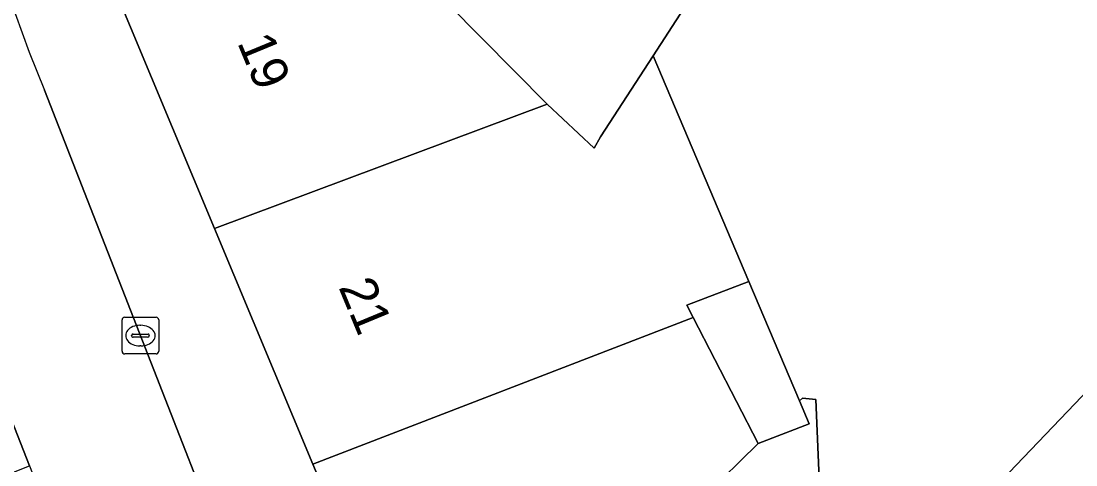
# Model space of a CAD drawing. Extents: x 160663 to 161506, y 382245 to 383291.
# Drawn here: x 161129.57 to 161158.3, y 383146.96 to 383159.05 of the extents above; entities that cross this region are included whole.
import ezdxf

# ---------------------------------------------------------------- set-up
doc = ezdxf.new("R2010")
doc.units = 0
for name, color, linetype in [('IMGEO_Groenvoorziening', 7, 'Continuous'), ('IMGEO_Kolk', 7, 'Continuous'), ('IMGEO_Pand', 7, 'Continuous'), ('IMGEO_Pand_nummerreeks', 7, 'Continuous'), ('IMGEO_Parkeervlak_open', 7, 'Continuous'), ('IMGEO_Voetpad_open', 7, 'Continuous'), ('IMGEO_Woonerf_open', 7, 'Continuous')]:
    doc.layers.add(name, color=color, linetype=linetype)

msp = doc.modelspace()

# ---------------------------------------------------------------- linework, layer by layer
at = {"layer": 'IMGEO_Groenvoorziening'}
for points in [[(161159.601, 383161.046), (161156.987, 383162.473), (161154.786, 383163.643), (161151.498, 383165.39), (161151.378, 383165.212), (161146.783, 383158.104), (161149.389, 383151.959), (161150.771, 383148.7), (161150.848, 383148.779), (161151.214, 383148.74), (161151.442, 383143.355), (161142.883, 383135.27), (161146.227, 383132.301), (161147.528, 383133.493), (161149.889, 383137.24), (161153.216, 383142.573), (161155.564, 383146.324), (161155.876, 383146.12), (161165.215, 383155.885)], [(161166.528, 383154.573), (161166.335, 383154.758), (161165.215, 383155.885), (161155.876, 383146.12), (161157.319, 383145.175), (161162.383, 383149.949), (161166.424, 383153.804)]]:
    msp.add_lwpolyline(points, dxfattribs=at)
at = {"layer": 'IMGEO_Kolk'}
for p, q in [((161132.323, 383150.055), (161132.323, 383150.907)), ((161132.398, 383150.981), (161133.25, 383150.981)), ((161132.811, 383150.761), (161132.836, 383150.761)), ((161133.324, 383150.907), (161133.324, 383150.055)), ((161132.582, 383150.475), (161132.582, 383150.487)), ((161132.625, 383150.524), (161133.023, 383150.524)), ((161133.066, 383150.487), (161133.066, 383150.475)), ((161133.02, 383150.438), (161132.622, 383150.438)), ((161132.834, 383150.201), (161132.809, 383150.201)), ((161133.25, 383149.981), (161132.398, 383149.981))]:
    msp.add_line(p, q, dxfattribs=at)
for points in [[(161132.323, 383150.055), (161132.323, 383150.907)], [(161132.398, 383150.981), (161133.25, 383150.981)], [(161133.324, 383150.907), (161133.324, 383150.055)], [(161133.25, 383149.981), (161132.398, 383149.981)]]:
    msp.add_lwpolyline(points, dxfattribs=at)
for centre, radius, start, end in [((161132.4, 383150.905), 0.0765, 91.552, 178.448), ((161132.4, 383150.905), 0.0765, 91.552, 178.448), ((161133.248, 383150.905), 0.0765, 1.552, 88.448), ((161133.248, 383150.905), 0.0765, 1.552, 88.448), ((161132.622, 383150.484), 0.0403, 85.8775, 175.7526), ((161132.619, 383150.474), 0.0366, 178.938, 274.7102), ((161133.023, 383150.481), 0.043, 264.8664, 352.4533), ((161133.027, 383150.486), 0.0386, 1.7309, 96.639), ((161132.4, 383150.057), 0.0765, 181.552, 268.448), ((161132.4, 383150.057), 0.0765, 181.552, 268.448), ((161133.248, 383150.057), 0.0765, 271.552, 358.448), ((161133.248, 383150.057), 0.0765, 271.552, 358.448)]:
    msp.add_arc(centre, radius, start, end, dxfattribs=at)
for centre, major_axis, ratio, start_param, end_param in [((161132.81, 383150.481), (-0.387, 0.002), 0.722429, 4.712389, 7.853982), ((161132.835, 383150.481), (-0.39, 0.002), 0.717154, 1.570796, 4.712389)]:
    msp.add_ellipse(centre, major_axis=major_axis, ratio=ratio, start_param=start_param, end_param=end_param, dxfattribs=at)
at = {"layer": 'IMGEO_Pand'}
for points in [[(161141.423, 383171.856), (161129.809, 383177.129), (161129.783, 383176.901), (161131.927, 383160.664), (161137.626, 383163.141), (161143.896, 383156.786), (161145.179, 383155.593), (161145.348, 383155.898), (161146.783, 383158.104), (161151.378, 383165.212), (161144.065, 383169.294), (161142.775, 383166.983), (161142.026, 383167.449)], [(161131.927, 383160.664), (161131.982, 383160.267), (161134.843, 383153.401), (161143.896, 383156.786), (161137.626, 383163.141)], [(161146.783, 383158.104), (161145.348, 383155.898), (161145.179, 383155.593), (161143.896, 383156.786), (161134.843, 383153.401), (161137.518, 383146.979), (161147.876, 383150.976), (161147.705, 383151.309), (161149.389, 383151.959)], [(161149.389, 383151.959), (161147.705, 383151.309), (161147.876, 383150.976), (161149.641, 383147.54), (161151.034, 383148.078), (161150.771, 383148.7)], [(161147.876, 383150.976), (161137.518, 383146.979), (161140.874, 383138.924), (161149.641, 383147.54)]]:
    msp.add_lwpolyline(points, close=True, dxfattribs=at)
at = {"layer": 'IMGEO_Parkeervlak_open'}
msp.add_lwpolyline([(161151.442, 383143.355), (161151.214, 383148.74), (161150.848, 383148.779), (161150.771, 383148.7), (161151.034, 383148.078), (161149.641, 383147.54), (161140.874, 383138.924), (161141.404, 383136.895), (161142.883, 383135.27)], close=True, dxfattribs=at)
at = {"layer": 'IMGEO_Voetpad_open'}
msp.add_lwpolyline([(161096.232, 383065.041), (161097.948, 383067.723), (161100.236, 383068.269), (161101.27, 383070.058), (161102.587, 383072.301), (161107.023, 383080.092), (161110.056, 383085.418), (161110.781, 383085.656), (161120.09, 383100.134), (161120.161, 383100.245), (161118.207, 383101.501), (161124.761, 383111.696), (161126.716, 383110.439), (161127.839, 383112.186), (161127.679, 383113.208), (161135.448, 383125.333), (161133.773, 383126.361), (161133.469, 383127.948), (161135.792, 383131.655), (161135.611, 383132.118), (161133.742, 383131.385), (161127.933, 383146.199), (161129.801, 383146.932), (161126.39, 383155.632)], dxfattribs=at)
at = {"layer": 'IMGEO_Woonerf_open'}
for points in [[(161137.518, 383146.979), (161134.843, 383153.401), (161131.982, 383160.267), (161131.927, 383160.664), (161129.783, 383176.901), (161129.809, 383177.129), (161130.489, 383183.198), (161130.789, 383183.88), (161131.314, 383185.435), (161134.132, 383192.246), (161135.412, 383195.339), (161136.378, 383197.673), (161136.869, 383198.648), (161139.406, 383203.684), (161139.801, 383204.468), (161139.653, 383204.63), (161138.74, 383205.154), (161143.158, 383214.429), (161142.031, 383214.987), (161141.728, 383215.125), (161141.644, 383214.953), (161140.933, 383213.502), (161130.888, 383192.701)], [(161126.39, 383155.632), (161129.801, 383146.932), (161134.356, 383135.317), (161134.733, 383136.197), (161137.382, 383137.217), (161138.12, 383136.927), (161130.21, 383157.169)], [(161130.21, 383157.169), (161138.12, 383136.927), (161139.034, 383134.588), (161140.349, 383131.225), (161142.362, 383129.951), (161143.189, 383129.962), (161146.791, 383130.012), (161148.063, 383130.922), (161146.227, 383132.301), (161142.883, 383135.27), (161141.404, 383136.895), (161140.874, 383138.924), (161137.518, 383146.979)]]:
    msp.add_lwpolyline(points, dxfattribs=at)
msp.add_arc((161171.449, 383174.177), 44.609, 179.4958, 202.4128, dxfattribs=at)
msp.add_arc((161171.449, 383174.177), 44.609, 179.4958, 202.4128, dxfattribs=at)

# ---------------------------------------------------------------- texts
at = {"layer": 'IMGEO_Pand_nummerreeks'}
for s, rotation, p in [('19', 292.4652, (161135.451, 383158.473)), ('21', 292.4941, (161138.209, 383151.805))]:
    msp.add_text(s, height=1, rotation=rotation, dxfattribs=at).set_placement(p)

doc.saveas('drawing.dxf')
